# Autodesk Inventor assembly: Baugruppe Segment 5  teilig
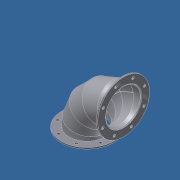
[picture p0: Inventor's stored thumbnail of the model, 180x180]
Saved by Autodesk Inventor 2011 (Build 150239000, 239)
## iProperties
Created: 2009-03
Part Number: Baugruppe Segment 5  teilig
Document SubType Name: Assembly
Designer: Guido Walteich
Mass: 4908.06 g
Surface Area: 3686.86 cm^2
Volume: 625.069 cm^3
Density: 7.85203 g/cm^3
Rohr_D: 160,0 mm
MITTEN_R: 160,0 mm
Wandstärke: 3,0 mm
ANZ_TEILE: 5,000 oersted
GES_WINKEL: 90,0 grd
Maße: = Ø<Rohr_D> x <Wandstärke>  R:<MITTEN_R>  Winkel:<GES_WINKEL>°
Author: Guido Walteich
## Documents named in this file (8)
- C:\Inventor ZeICHNUNGEN\AFL\Auftragsbezogen\Nasswäscher_AFL--Projekt-A1442-Kunde HPL\Workspaces\Arbeitsbereich\SEGMENTBOGEN\Baugruppe Segment 5  teilig.iam
- C:\Inventor ZeICHNUNGEN\AFL\Auftragsbezogen\Nasswäscher_AFL--Projekt-A1442-Kunde HPL\Workspaces\Arbeitsbereich\SEGMENTBOGEN\Bauteil_Segment_1.ipt
- C:\Inventor ZeICHNUNGEN\AFL\Auftragsbezogen\Nasswäscher_AFL--Projekt-A1442-Kunde HPL\Workspaces\Arbeitsbereich\SEGMENTBOGEN\Bauteil_Segment_5.ipt
- C:\Inventor ZeICHNUNGEN\AFL\Auftragsbezogen\Nasswäscher_AFL--Projekt-A1442-Kunde HPL\Workspaces\Arbeitsbereich\SEGMENTBOGEN\Bauteil_Segment_2.ipt
- C:\Inventor ZeICHNUNGEN\AFL\Auftragsbezogen\Nasswäscher_AFL--Projekt-A1442-Kunde HPL\Workspaces\Arbeitsbereich\SEGMENTBOGEN\Bauteil_Segment_3.ipt
- C:\Inventor ZeICHNUNGEN\AFL\Auftragsbezogen\Nasswäscher_AFL--Projekt-A1442-Kunde HPL\Workspaces\Arbeitsbereich\SEGMENTBOGEN\Bauteil_Segment_4.ipt
- D:\Zeichnungen----Inventor\AFL\Nasswäscher-AFL-A-1442\Workspaces\Arbeitsbereich\Flansch DIN 24154-R2.ipt
- C:\Inventor ZeICHNUNGEN\AFL\Auftragsbezogen\Nasswäscher_AFL--Projekt-A1442-Kunde HPL\Workspaces\Arbeitsbereich\Flansch DIN 24154-R2\Flansch DIN 24154-R2-160.ipt
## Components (7 placed, 6 different names)
1. Bauteil_Segment_1:1 — Passend:1, Passend:2, Fluchtend:1, Passend:10, Passend:11, Passend:12
2. Bauteil_Segment_5:1 — Passend:7, Passend:8, Passend:9, Passend:13, Passend:14, Passend:15
3. Bauteil_Segment_2:1 — Passend:1, Passend:2, Fluchtend:1, Passend:3, Passend:4, Fluchtend:2
4. Bauteil_Segment_3:1 — Passend:3, Passend:4, Fluchtend:2, Passend:5, Passend:6, Fluchtend:3
5. Bauteil_Segment_4:1 — Passend:5, Passend:6, Fluchtend:3, Passend:7, Passend:8, Passend:9
6. Flansch DIN 24154-R2-160:1 — Passend:10, Passend:11, Passend:12
7. Flansch DIN 24154-R2-160:2 — Passend:13, Passend:14, Passend:15
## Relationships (18: Mate 15, Flush 3)
- Passend:1 [Mate]: Bauteil_Segment_1:1 ↔ Bauteil_Segment_2:1
- Passend:2 [Mate]: Bauteil_Segment_1:1 ↔ Bauteil_Segment_2:1
- Fluchtend:1 [Flush]: Bauteil_Segment_1:1 ↔ Bauteil_Segment_2:1
- Passend:3 [Mate]: Bauteil_Segment_2:1 ↔ Bauteil_Segment_3:1
- Passend:4 [Mate]: Bauteil_Segment_2:1 ↔ Bauteil_Segment_3:1
- Fluchtend:2 [Flush]: Bauteil_Segment_2:1 ↔ Bauteil_Segment_3:1
- Passend:5 [Mate]: Bauteil_Segment_3:1 ↔ Bauteil_Segment_4:1
- Passend:6 [Mate]: Bauteil_Segment_3:1 ↔ Bauteil_Segment_4:1
- Fluchtend:3 [Flush]: Bauteil_Segment_3:1 ↔ Bauteil_Segment_4:1
- Passend:7 [Mate]: Bauteil_Segment_5:1 ↔ Bauteil_Segment_4:1
- Passend:8 [Mate]: Bauteil_Segment_5:1 ↔ Bauteil_Segment_4:1
- Passend:9 [Mate]: Bauteil_Segment_5:1 ↔ Bauteil_Segment_4:1
- Passend:10 [Mate]: Bauteil_Segment_1:1 ↔ Flansch DIN 24154-R2-160:1
- Passend:11 [Mate]: Bauteil_Segment_1:1 ↔ Flansch DIN 24154-R2-160:1
- Passend:12 [Mate]: Bauteil_Segment_1:1 ↔ Flansch DIN 24154-R2-160:1
- Passend:13 [Mate]: Bauteil_Segment_5:1 ↔ Flansch DIN 24154-R2-160:2
- Passend:14 [Mate]: Bauteil_Segment_5:1 ↔ Flansch DIN 24154-R2-160:2
- Passend:15 [Mate]: Bauteil_Segment_5:1 ↔ Flansch DIN 24154-R2-160:2
## Named parameters: WINKEL = 1.9635 mm, Länge_1 = 47.73896 mm, Länge_2 = 95.47792 mm, Länge_3 = 95.47792 mm, Länge_4 = 95.47792 mm, Länge_5 = 47.73896 mm, Wandstärke = 3 mm, GES_WINKEL = 90 deg, ANZ_TEILE = 39.78874 mm
